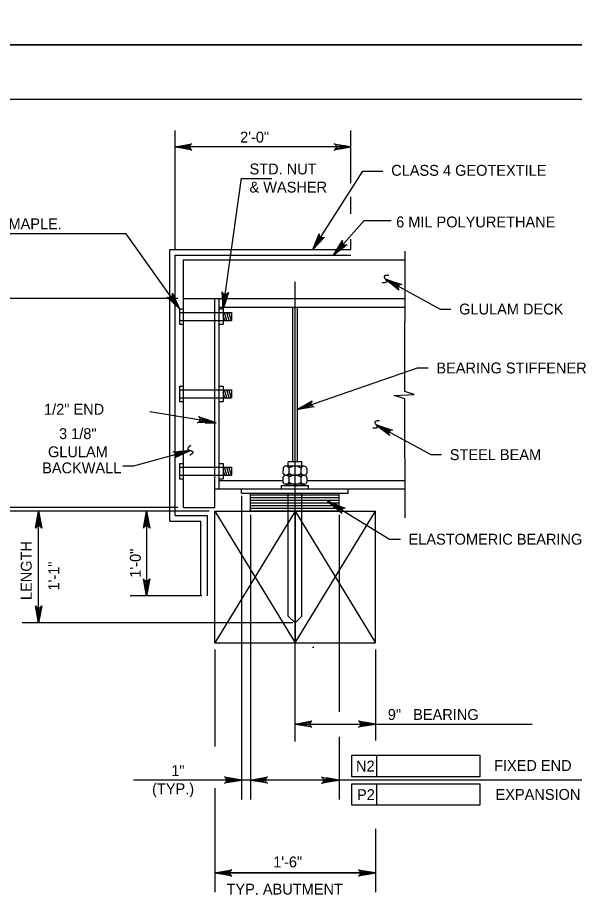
# Model space of a CAD drawing. Extents: x 638175 to 640495, y 294277 to 298435.
# Drawn here: x 639423 to 639576.6, y 297011.5 to 297255 of the extents above; entities that cross this region are included whole.
import ezdxf

# ---------------------------------------------------------------- set-up
doc = ezdxf.new("R2010")
doc.units = 0
for name, color, linetype in [('2', 7, 'Continuous'), ('3', 7, 'Continuous'), ('4', 7, 'Continuous'), ('5', 7, 'Continuous'), ('PLT-BNDY', 7, 'Continuous')]:
    doc.layers.add(name, color=color, linetype=linetype)

# ---------------------------------------------------------------- blocks, each defined once
blk = doc.blocks.new('25S')
at = {"layer": '4'}
blk.add_open_spline([(-1.68325, 0.611625), (-0.867125, -1.69875), (0.901125, 1.69875), (1.58125, -0.611625)], degree=2, dxfattribs=at)

msp = doc.modelspace()

# ---------------------------------------------------------------- linework, layer by layer
at = {"layer": '2'}
msp.add_line((639316.46, 297232.46), (640102.46, 297232.46), dxfattribs=at)
at = {"layer": '3'}
for p, q in [((639466.43, 297190.99), (639466.43, 297223.82)), ((639514.95, 297209.35), (639514.95, 297223.82)), ((639514.95, 297219.32), (639466.43, 297219.32)), ((639518.2, 297212.58), (639523.72, 297212.58)), ((639484.7, 297210.6), (639493.11, 297210.6)), ((639514.95, 297200.87), (639514.95, 297205.52)), ((639518.58, 297199.02), (639526.07, 297199.02)), ((639452.93, 297195.36), (639331.55, 297195.36)), ((639514.95, 297190.99), (639514.95, 297193.91)), ((639529.85, 297151.9), (639529.89, 297190.53)), ((639524.45, 297182.85), (639539.53, 297174.6)), ((639467.22, 297177.48), (639395.13, 297177.48)), ((639539.53, 297174.6), (639542.53, 297174.6)), ((639500.13, 297146.93), (639533.26, 297158.35)), ((639533.26, 297158.35), (639536.26, 297158.35)), ((639526.84, 297150.74), (639532.36, 297151.05)), ((639532.36, 297151.05), (639529.85, 297151.9)), ((639529.85, 297149.86), (639526.84, 297150.74)), ((639529.89, 297117.06), (639529.85, 297149.86)), ((639477.39, 297143.33), (639459.46, 297146.29)), ((639521.87, 297142.71), (639536.96, 297134.46)), ((639470.68, 297135.6), (639455, 297131.32)), ((639536.96, 297134.46), (639539.96, 297134.46)), ((639455, 297131.32), (639452, 297131.32)), ((639484.77, 297123.1), (639484.77, 297039.4)), ((639467.22, 297119.86), (639395.13, 297119.86)), ((639508.94, 297121.38), (639525.58, 297111.13)), ((639475.83, 297118.87), (639395.13, 297118.87)), ((639467.22, 297118.87), (639424.3, 297118.87)), ((639427.24, 297118.87), (639424.3, 297118.87)), ((639428.8, 297088.06), (639428.8, 297118.87)), ((639461.93, 297118.87), (639454.08, 297118.87)), ((639459.15, 297118.87), (639454.08, 297118.87)), ((639458.58, 297118.87), (639458.58, 297095.56)), ((639487.23, 297117.88), (639487.23, 297039.4)), ((639511.7, 297117.88), (639511.7, 297063.57)), ((639428.8, 297091.06), (639428.8, 297115.87)), ((639458.58, 297115.87), (639458.58, 297098.56)), ((639525.58, 297111.13), (639528.58, 297111.13)), ((639473.83, 297095.56), (639454.08, 297095.56)), ((639459.15, 297095.56), (639454.08, 297095.56)), ((639498.91, 297088.06), (639424.3, 297088.06)), ((639427.24, 297088.06), (639424.3, 297088.06)), ((639477.39, 297080.74), (639477.39, 297053.94)), ((639521.69, 297080.74), (639521.69, 297056.81)), ((639499.54, 297061.72), (639499.54, 297064.66)), ((639499.54, 297060.16), (639528.77, 297060.16)), ((639502.54, 297060.16), (639518.69, 297060.16)), ((639521.69, 297058.59), (639521.69, 297055.66)), ((639528.77, 297060.16), (639564.9, 297060.16)), ((639511.7, 297056.64), (639511.7, 297039.4)), ((639515.17, 297051.55), (639550.47, 297051.55)), ((639515.17, 297045.64), (639515.17, 297051.55)), ((639522.06, 297045.64), (639522.06, 297051.55)), ((639550.47, 297051.55), (639550.47, 297045.64)), ((639587.69, 297044.71), (639454.93, 297044.71)), ((639550.47, 297045.64), (639515.17, 297045.64)), ((639477.39, 297042.47), (639477.39, 297013.78)), ((639515.17, 297043.67), (639550.47, 297043.67)), ((639515.17, 297037.76), (639515.17, 297043.67)), ((639522.06, 297037.76), (639522.06, 297043.67)), ((639550.47, 297043.67), (639550.47, 297037.76)), ((639550.47, 297037.76), (639515.17, 297037.76)), ((639521.69, 297031.3), (639521.69, 297013.78)), ((639477.39, 297025.38), (639477.39, 297014.6)), ((639521.69, 297020.99), (639521.69, 297014.6)), ((639521.69, 297019.1), (639477.39, 297019.1)), ((639480.39, 297019.1), (639518.69, 297019.1))]:
    msp.add_line(p, q, dxfattribs=at)
for points in [[(639466.43, 297219.32), (639471.09, 297220.19), (639470.73, 297219.95), (639470.55, 297219.63), (639470.49, 297219.32), (639470.55, 297219.01), (639470.73, 297218.7), (639471.09, 297218.45), (639466.43, 297219.32), (639470.73, 297218.7), (639470.55, 297219.01), (639466.43, 297219.32), (639470.49, 297219.32), (639470.55, 297219.63), (639466.43, 297219.32), (639470.73, 297219.95)], [(639514.95, 297219.32), (639510.29, 297218.45), (639510.65, 297218.7), (639510.84, 297219.01), (639510.89, 297219.32), (639510.84, 297219.63), (639510.65, 297219.95), (639510.29, 297220.19), (639514.95, 297219.32), (639510.65, 297219.95), (639510.84, 297219.63), (639514.95, 297219.32), (639510.89, 297219.32), (639510.84, 297219.01), (639514.95, 297219.32), (639510.65, 297218.7)], [(639504.39, 297190.98), (639518.2, 297212.58)], [(639479.67, 297174.64), (639484.72, 297210.73)], [(639510.16, 297189.43), (639518.58, 297199.02)], [(639467.69, 297174.64), (639452.93, 297195.36)], [(639504.39, 297190.98), (639506.16, 297195.37), (639506.18, 297194.94), (639506.34, 297194.61), (639506.58, 297194.4), (639506.87, 297194.28), (639507.23, 297194.26), (639507.63, 297194.43), (639504.39, 297190.98), (639507.23, 297194.26), (639506.87, 297194.28), (639504.39, 297190.98), (639506.58, 297194.4), (639506.34, 297194.61), (639504.39, 297190.98), (639506.18, 297194.94)], [(639510.16, 297189.43), (639512.57, 297193.51), (639512.52, 297193.07), (639512.64, 297192.73), (639512.84, 297192.48), (639513.11, 297192.32), (639513.46, 297192.25), (639513.89, 297192.35), (639510.16, 297189.43), (639513.46, 297192.25), (639513.11, 297192.32), (639510.16, 297189.43), (639512.84, 297192.48), (639512.64, 297192.73), (639510.16, 297189.43), (639512.52, 297193.07)], [(639524.45, 297182.85), (639528.96, 297181.38), (639528.52, 297181.33), (639528.21, 297181.15), (639528.01, 297180.9), (639527.91, 297180.6), (639527.92, 297180.24), (639528.12, 297179.85), (639524.45, 297182.85), (639527.92, 297180.24), (639527.91, 297180.6), (639524.45, 297182.85), (639528.01, 297180.9), (639528.21, 297181.15), (639524.45, 297182.85), (639528.52, 297181.33)], [(639467.69, 297174.64), (639464.27, 297177.92), (639464.68, 297177.78), (639465.05, 297177.81), (639465.33, 297177.94), (639465.55, 297178.17), (639465.7, 297178.5), (639465.7, 297178.94), (639467.69, 297174.64), (639465.7, 297178.5), (639465.55, 297178.17), (639467.69, 297174.64), (639465.33, 297177.94), (639465.05, 297177.81), (639467.69, 297174.64), (639464.68, 297177.78)], [(639479.67, 297174.64), (639479.45, 297179.37), (639479.64, 297178.98), (639479.93, 297178.75), (639480.23, 297178.66), (639480.55, 297178.67), (639480.88, 297178.81), (639481.18, 297179.13), (639479.67, 297174.64), (639480.88, 297178.81), (639480.55, 297178.67), (639479.67, 297174.64), (639480.23, 297178.66), (639479.93, 297178.75), (639479.67, 297174.64), (639479.64, 297178.98)], [(639500.13, 297146.93), (639504.25, 297149.28), (639503.99, 297148.92), (639503.92, 297148.57), (639503.97, 297148.26), (639504.13, 297147.98), (639504.4, 297147.74), (639504.82, 297147.62), (639500.13, 297146.93), (639504.4, 297147.74), (639504.13, 297147.98), (639500.13, 297146.93), (639503.97, 297148.26), (639503.92, 297148.57), (639500.13, 297146.93), (639503.99, 297148.92)], [(639477.39, 297143.33), (639472.65, 297143.23), (639473.05, 297143.42), (639473.28, 297143.7), (639473.39, 297144), (639473.38, 297144.31), (639473.25, 297144.65), (639472.94, 297144.95), (639477.39, 297143.33), (639473.25, 297144.65), (639473.38, 297144.31), (639477.39, 297143.33), (639473.39, 297144), (639473.28, 297143.7), (639477.39, 297143.33), (639473.05, 297143.42)], [(639521.87, 297142.71), (639526.38, 297141.24), (639525.95, 297141.19), (639525.63, 297141.01), (639525.44, 297140.76), (639525.33, 297140.46), (639525.35, 297140.1), (639525.54, 297139.71), (639521.87, 297142.71), (639525.35, 297140.1), (639525.33, 297140.46), (639521.87, 297142.71), (639525.44, 297140.76), (639525.63, 297141.01), (639521.87, 297142.71), (639525.95, 297141.19)], [(639470.68, 297135.6), (639466.41, 297133.53), (639466.69, 297133.87), (639466.79, 297134.22), (639466.76, 297134.53), (639466.63, 297134.82), (639466.37, 297135.07), (639465.95, 297135.22), (639470.68, 297135.6), (639466.37, 297135.07), (639466.63, 297134.82), (639470.68, 297135.6), (639466.76, 297134.53), (639466.79, 297134.22), (639470.68, 297135.6), (639466.69, 297133.87)], [(639508.94, 297121.38), (639513.37, 297119.68), (639512.93, 297119.66), (639512.61, 297119.49), (639512.4, 297119.25), (639512.28, 297118.96), (639512.28, 297118.59), (639512.45, 297118.19), (639508.94, 297121.38), (639512.28, 297118.59), (639512.28, 297118.96), (639508.94, 297121.38), (639512.4, 297119.25), (639512.61, 297119.49), (639508.94, 297121.38), (639512.93, 297119.66)], [(639428.8, 297118.87), (639429.68, 297114.21), (639429.43, 297114.57), (639429.12, 297114.76), (639428.8, 297114.81), (639428.49, 297114.76), (639428.18, 297114.57), (639427.93, 297114.21), (639428.8, 297118.87), (639428.18, 297114.57), (639428.49, 297114.76), (639428.8, 297118.87), (639428.8, 297114.81), (639429.12, 297114.76), (639428.8, 297118.87), (639429.43, 297114.57)], [(639458.58, 297118.87), (639459.45, 297114.21), (639459.2, 297114.57), (639458.89, 297114.76), (639458.58, 297114.81), (639458.26, 297114.76), (639457.95, 297114.57), (639457.7, 297114.21), (639458.58, 297118.87), (639457.95, 297114.57), (639458.26, 297114.76), (639458.58, 297118.87), (639458.58, 297114.81), (639458.89, 297114.76), (639458.58, 297118.87), (639459.2, 297114.57)], [(639458.58, 297095.56), (639457.7, 297100.22), (639457.95, 297099.86), (639458.26, 297099.67), (639458.58, 297099.62), (639458.89, 297099.67), (639459.2, 297099.86), (639459.45, 297100.22), (639458.58, 297095.56), (639459.2, 297099.86), (639458.89, 297099.67), (639458.58, 297095.56), (639458.58, 297099.62), (639458.26, 297099.67), (639458.58, 297095.56), (639457.95, 297099.86)], [(639428.8, 297088.06), (639427.93, 297092.72), (639428.18, 297092.36), (639428.49, 297092.18), (639428.8, 297092.12), (639429.12, 297092.18), (639429.43, 297092.36), (639429.68, 297092.72), (639428.8, 297088.06), (639429.43, 297092.36), (639429.12, 297092.18), (639428.8, 297088.06), (639428.8, 297092.12), (639428.49, 297092.18), (639428.8, 297088.06), (639428.18, 297092.36)], [(639499.54, 297060.16), (639504.2, 297061.03), (639503.84, 297060.78), (639503.66, 297060.47), (639503.6, 297060.16), (639503.66, 297059.84), (639503.84, 297059.53), (639504.2, 297059.28), (639499.54, 297060.16), (639503.84, 297059.53), (639503.66, 297059.84), (639499.54, 297060.16), (639503.6, 297060.16), (639503.66, 297060.47), (639499.54, 297060.16), (639503.84, 297060.78)], [(639521.69, 297060.16), (639517.03, 297059.28), (639517.39, 297059.53), (639517.57, 297059.84), (639517.63, 297060.16), (639517.57, 297060.47), (639517.39, 297060.78), (639517.03, 297061.03), (639521.69, 297060.16), (639517.39, 297060.78), (639517.57, 297060.47), (639521.69, 297060.16), (639517.63, 297060.16), (639517.57, 297059.84), (639521.69, 297060.16), (639517.39, 297059.53)], [(639484.71, 297044.7), (639480.04, 297043.83), (639480.4, 297044.08), (639480.59, 297044.39), (639480.64, 297044.7), (639480.59, 297045.02), (639480.4, 297045.33), (639480.04, 297045.58), (639484.71, 297044.7), (639480.4, 297045.33), (639480.59, 297045.02), (639484.71, 297044.7), (639480.64, 297044.7), (639480.59, 297044.39), (639484.71, 297044.7), (639480.4, 297044.08)], [(639487.23, 297044.71), (639491.89, 297045.59), (639491.53, 297045.34), (639491.35, 297045.03), (639491.29, 297044.71), (639491.35, 297044.4), (639491.53, 297044.09), (639491.89, 297043.84), (639487.23, 297044.71), (639491.53, 297044.09), (639491.35, 297044.4), (639487.23, 297044.71), (639491.29, 297044.71), (639491.35, 297045.03), (639487.23, 297044.71), (639491.53, 297045.34)], [(639511.49, 297044.68), (639506.83, 297043.81), (639507.18, 297044.05), (639507.37, 297044.37), (639507.42, 297044.68), (639507.37, 297044.99), (639507.18, 297045.3), (639506.83, 297045.55), (639511.49, 297044.68), (639507.18, 297045.3), (639507.37, 297044.99), (639511.49, 297044.68), (639507.42, 297044.68), (639507.37, 297044.37), (639511.49, 297044.68), (639507.18, 297044.05)]]:
    msp.add_lwpolyline(points, dxfattribs=at)
for points in [[(639469.43, 297219.82), (639469.43, 297218.82), (639466.43, 297219.32)], [(639511.95, 297219.82), (639511.95, 297218.82), (639514.95, 297219.32)], [(639504.39, 297190.98), (639506.21, 297193.37), (639505.79, 297193.64)], [(639510.16, 297189.43), (639512.32, 297191.52), (639511.95, 297191.85)], [(639526.84, 297180.97), (639527.32, 297181.85), (639524.45, 297182.85)], [(639467.69, 297174.64), (639466.15, 297177.22), (639465.74, 297176.93)], [(639479.67, 297174.64), (639480.33, 297177.57), (639479.84, 297177.64)], [(639503.25, 297147.48), (639502.92, 297148.42), (639500.25, 297146.97)], [(639474.89, 297144.25), (639474.73, 297143.27), (639477.77, 297143.27)], [(639524.27, 297140.83), (639524.75, 297141.7), (639521.88, 297142.71)], [(639467.63, 297135.29), (639467.89, 297134.32), (639470.65, 297135.59)], [(639510.79, 297119.65), (639511.32, 297120.5), (639508.5, 297121.65)], [(639428.3, 297115.87), (639429.3, 297115.87), (639428.8, 297118.87)], [(639458.08, 297115.87), (639459.08, 297115.87), (639458.58, 297118.87)], [(639458.08, 297098.56), (639459.08, 297098.56), (639458.58, 297095.56)], [(639428.3, 297091.06), (639429.3, 297091.06), (639428.8, 297088.06)], [(639502.54, 297060.66), (639502.54, 297059.66), (639499.54, 297060.16)], [(639518.69, 297060.66), (639518.69, 297059.66), (639521.69, 297060.16)], [(639481.23, 297045.3), (639481.23, 297044.12), (639484.77, 297044.71)], [(639490.78, 297045.3), (639490.78, 297044.12), (639487.23, 297044.71)], [(639508.15, 297045.3), (639508.15, 297044.12), (639511.7, 297044.71)], [(639480.39, 297019.6), (639480.39, 297018.6), (639477.39, 297019.1)], [(639518.69, 297019.6), (639518.69, 297018.6), (639521.69, 297019.1)]]:
    msp.add_lwpolyline(points, close=True, dxfattribs=at)
at = {"layer": '4'}
for p, q in [((639467.69, 297174.64), (639468.78, 297174.64)), ((639467.69, 297174.64), (639467.69, 297170.47)), ((639467.69, 297173.65), (639478.58, 297173.65)), ((639478.58, 297174.64), (639479.67, 297174.64)), ((639478.58, 297173.65), (639481.99, 297173.65)), ((639479.67, 297174.64), (639479.67, 297170.47)), ((639480.13, 297171.46), (639479.67, 297172.9)), ((639480.75, 297171.46), (639480.05, 297173.65)), ((639481.37, 297171.46), (639480.67, 297173.65)), ((639481.99, 297171.46), (639481.29, 297173.65)), ((639481.99, 297173.65), (639481.99, 297171.46)), ((639500.13, 297175.13), (639500.13, 297132.43)), ((639467.69, 297171.46), (639478.58, 297171.46)), ((639467.69, 297170.47), (639468.78, 297170.47)), ((639478.58, 297171.46), (639481.99, 297171.46)), ((639478.58, 297170.47), (639479.67, 297170.47)), ((639467.69, 297153.31), (639467.69, 297149.15)), ((639467.69, 297153.31), (639468.78, 297153.31)), ((639467.69, 297152.32), (639478.58, 297152.32)), ((639478.58, 297153.31), (639479.67, 297153.31)), ((639478.58, 297152.32), (639481.99, 297152.32)), ((639479.67, 297153.31), (639479.67, 297149.15)), ((639480.13, 297150.13), (639479.67, 297151.57)), ((639480.75, 297150.13), (639480.05, 297152.32)), ((639481.37, 297150.13), (639480.67, 297152.32)), ((639481.99, 297150.13), (639481.29, 297152.32)), ((639481.99, 297152.32), (639481.99, 297150.13)), ((639467.69, 297150.13), (639478.58, 297150.13)), ((639467.69, 297149.15), (639468.78, 297149.15)), ((639478.58, 297150.13), (639481.99, 297150.13)), ((639478.58, 297149.15), (639479.67, 297149.15)), ((639467.69, 297131.98), (639468.78, 297131.98)), ((639467.69, 297131.98), (639467.69, 297127.82)), ((639478.58, 297131.98), (639479.67, 297131.98)), ((639479.67, 297131.98), (639479.67, 297127.82)), ((639467.69, 297130.99), (639478.58, 297130.99)), ((639478.58, 297130.99), (639481.99, 297130.99)), ((639480.13, 297128.8), (639479.67, 297130.25)), ((639480.75, 297128.8), (639480.05, 297130.99)), ((639481.37, 297128.8), (639480.67, 297130.99)), ((639481.99, 297128.8), (639481.29, 297130.99)), ((639481.99, 297130.99), (639481.99, 297128.8)), ((639467.69, 297128.8), (639478.58, 297128.8)), ((639467.69, 297127.82), (639468.78, 297127.82)), ((639478.58, 297128.8), (639481.99, 297128.8)), ((639478.58, 297127.82), (639479.67, 297127.82)), ((639514.05, 297083), (639514.05, 297083)), ((639521.65, 297083.41), (639521.65, 297083.41)), ((639501.64, 297081.37), (639501.64, 297081.37)), ((639504.34, 297081.16), (639504.58, 297081.45)), ((639504.63, 297081.19), (639504.59, 297081.45)), ((639505.37, 297081.86), (639505.37, 297081.86)), ((639516.68, 297082.77), (639516.68, 297082.77)), ((639486.77, 297079.41), (639486.77, 297079.41))]:
    msp.add_line(p, q, dxfattribs=at)
for points in [[(639477.39, 297019.1), (639482.06, 297019.97), (639481.7, 297019.72), (639481.51, 297019.41), (639481.46, 297019.1), (639481.51, 297018.78), (639481.7, 297018.47), (639482.06, 297018.22), (639477.39, 297019.1), (639481.7, 297018.47), (639481.51, 297018.78), (639477.39, 297019.1), (639481.46, 297019.1), (639481.51, 297019.41), (639477.39, 297019.1), (639481.7, 297019.72)], [(639521.69, 297019.1), (639517.03, 297018.22), (639517.39, 297018.47), (639517.57, 297018.78), (639517.63, 297019.1), (639517.57, 297019.41), (639517.39, 297019.72), (639517.03, 297019.97), (639521.69, 297019.1), (639517.39, 297019.72), (639517.57, 297019.41), (639521.69, 297019.1), (639517.63, 297019.1), (639517.57, 297018.78), (639521.69, 297019.1), (639517.39, 297018.47)]]:
    msp.add_lwpolyline(points, dxfattribs=at)
at = {"layer": '5'}
for p, q in [((639465.04, 297190.98), (639514.95, 297190.98)), ((639465.04, 297116.12), (639465.04, 297190.98)), ((639466.43, 297189.43), (639514.95, 297189.43)), ((639466.43, 297117.67), (639466.43, 297189.43)), ((639468.78, 297119.86), (639468.78, 297188.15)), ((639468.78, 297188.15), (639529.88, 297188.15)), ((639499.54, 297055.36), (639499.54, 297182.14)), ((639468.78, 297177.48), (639529.88, 297177.48)), ((639477.39, 297119.86), (639477.39, 297177.48)), ((639478.58, 297124.98), (639478.58, 297177.48)), ((639478.58, 297175.13), (639529.88, 297175.13)), ((639498.95, 297132.43), (639498.95, 297175.13)), ((639497.67, 297131.28), (639497.67, 297132.44)), ((639501.42, 297132.43), (639497.67, 297132.44)), ((639501.42, 297131.27), (639501.42, 297132.43)), ((639496.21, 297130.7), (639496.2, 297129.36)), ((639502.01, 297131.27), (639497.03, 297131.28)), ((639497.9, 297129.36), (639497.91, 297130.7)), ((639501.18, 297129.35), (639501.19, 297130.69)), ((639502.77, 297130.69), (639502.77, 297129.35)), ((639478.58, 297127.32), (639496.2, 297127.32)), ((639496.2, 297128.2), (639496.2, 297126.86)), ((639502, 297128.77), (639497.02, 297128.78)), ((639497.9, 297126.86), (639497.9, 297128.2)), ((639501.18, 297126.85), (639501.18, 297128.19)), ((639502.76, 297128.19), (639502.76, 297126.85)), ((639502.76, 297127.32), (639529.88, 297127.32)), ((639477.39, 297124.98), (639529.88, 297124.98)), ((639484.77, 297123.8), (639484.77, 297124.98)), ((639495.8, 297125.96), (639503.28, 297125.96)), ((639495.8, 297124.98), (639495.8, 297125.96)), ((639502, 297126.27), (639497.02, 297126.28)), ((639497.67, 297125.96), (639497.67, 297126.28)), ((639501.42, 297125.96), (639501.42, 297126.27)), ((639503.28, 297124.98), (639503.28, 297125.96)), ((639514.16, 297123.8), (639514.16, 297124.98)), ((639484.77, 297123.8), (639514.16, 297123.8)), ((639487.23, 297118.87), (639487.23, 297123.8)), ((639487.23, 297123.4), (639497.67, 297123.4)), ((639487.23, 297122.66), (639497.67, 297122.66)), ((639487.23, 297121.92), (639497.67, 297121.92)), ((639497.67, 297118.87), (639497.67, 297123.8)), ((639497.67, 297123.4), (639499.54, 297123.4)), ((639497.67, 297122.66), (639499.54, 297122.66)), ((639497.67, 297121.92), (639499.54, 297121.92)), ((639499.54, 297123.4), (639501.42, 297123.4)), ((639499.54, 297122.66), (639501.42, 297122.66)), ((639499.54, 297121.92), (639501.42, 297121.92)), ((639501.42, 297118.87), (639501.42, 297123.8)), ((639501.42, 297123.4), (639511.7, 297123.4)), ((639501.42, 297122.66), (639511.7, 297122.66)), ((639501.42, 297121.92), (639511.7, 297121.92)), ((639511.7, 297118.87), (639511.7, 297123.8)), ((639468.78, 297119.86), (639477.39, 297119.86)), ((639487.23, 297121.18), (639497.67, 297121.18)), ((639487.23, 297120.45), (639497.67, 297120.45)), ((639487.23, 297119.71), (639497.67, 297119.71)), ((639497.67, 297121.18), (639499.54, 297121.18)), ((639497.67, 297120.45), (639499.54, 297120.45)), ((639497.67, 297119.71), (639499.54, 297119.71)), ((639499.54, 297121.18), (639501.42, 297121.18)), ((639499.54, 297120.45), (639501.42, 297120.45)), ((639499.54, 297119.71), (639501.42, 297119.71)), ((639501.42, 297121.18), (639511.7, 297121.18)), ((639501.42, 297120.45), (639511.7, 297120.45)), ((639501.42, 297119.71), (639511.7, 297119.71)), ((639466.43, 297117.67), (639475.39, 297117.67)), ((639475.39, 297095.56), (639475.39, 297117.67)), ((639477.39, 297082.58), (639477.39, 297118.87)), ((639477.39, 297118.87), (639521.69, 297118.87)), ((639499.54, 297118.87), (639477.39, 297082.58)), ((639477.39, 297118.87), (639499.54, 297082.58)), ((639487.23, 297118.97), (639497.67, 297118.97)), ((639497.67, 297118.97), (639499.54, 297118.97)), ((639497.67, 297089.92), (639497.67, 297118.87)), ((639499.54, 297118.97), (639501.42, 297118.97)), ((639499.54, 297082.58), (639521.69, 297118.87)), ((639499.54, 297118.87), (639521.69, 297082.58)), ((639499.54, 297118.87), (639499.54, 297082.58)), ((639501.42, 297118.97), (639511.7, 297118.97)), ((639501.42, 297089.9), (639501.42, 297118.87)), ((639521.69, 297082.84), (639521.69, 297118.87)), ((639465.04, 297116.12), (639473.53, 297116.12)), ((639473.53, 297095.56), (639473.53, 297116.12)), ((639499.55, 297088.04), (639497.66, 297089.92)), ((639499.55, 297088.04), (639501.41, 297089.9)), ((639477.39, 297082.58), (639521.69, 297082.58))]:
    msp.add_line(p, q, dxfattribs=at)
for centre, radius, start, end in [((639497.05, 297129.69), 0.912, 201.1685, 271.7086), ((639497.05, 297130.37), 0.912, 88.0545, 158.5946), ((639497.05, 297130.37), 0.912, 21.1685, 88.0545), ((639497.05, 297129.69), 0.912, 271.7086, 338.5946), ((639499.54, 297128.67), 2.61, 50.9315, 128.8315), ((639499.55, 297131.39), 2.61, 230.9315, 308.8315), ((639501.97, 297129.6), 0.829, 197.3333, 342.4297), ((639501.98, 297130.44), 0.829, 17.3333, 162.4297), ((639497.05, 297127.87), 0.912, 88.0545, 158.5946), ((639497.05, 297127.19), 0.912, 201.1685, 271.7086), ((639497.05, 297127.19), 0.912, 271.7086, 338.5946), ((639497.05, 297127.87), 0.912, 21.1685, 88.0545), ((639499.54, 297126.17), 2.61, 50.9315, 128.8315), ((639499.54, 297128.89), 2.61, 230.9315, 308.8315), ((639501.97, 297127.94), 0.829, 17.3333, 162.4297), ((639501.97, 297127.1), 0.829, 197.3333, 342.4297)]:
    msp.add_arc(centre, radius, start, end, dxfattribs=at)
at = {"layer": 'PLT-BNDY'}
for points in [[(639276.46, 297841.46), (640117.46, 297841.46), (640117.46, 297247.46), (639276.46, 297247.46)], [(639276.46, 297247.46), (640117.46, 297247.46), (640117.46, 296653.46), (639276.46, 296653.46)]]:
    msp.add_lwpolyline(points, close=True, dxfattribs=at)

# ---------------------------------------------------------------- block references
at = {"layer": '4', "yscale": 0.7874015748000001}
for p, xscale, rotation in [((639524.45, 297182.85), 0.7874015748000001, -112.31681079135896), ((639521.88, 297142.71), 0.7874015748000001, -112.31681079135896), ((639470.65, 297135.59), 0.7874015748, -74.14105771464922)]:
    msp.add_blockref('25S', p, dxfattribs=dict(at, xscale=xscale, rotation=rotation))

# ---------------------------------------------------------------- texts
at = {"layer": '3'}
for s, p in [('2\'-0"', (639484.38, 297220.52)), ('STD. NUT', (639486.97, 297211.73)), ('CLASS 4 GEOTEXTILE', (639526.05, 297211.35)), ('& WASHER', (639486.97, 297206.73)), ('WASHER FOR NORTHERN RED OAK AND RED MAPLE.', (639330, 297196.62)), ('6 MIL POLYURETHANE', (639527.41, 297197.12)), ('GLULAM DECK', (639544.78, 297173.1)), ('BEARING STIFFENER', (639538.51, 297156.85)), ('1/2" END  ', (639430.3, 297145.47)), ('3 1/8"', (639434.44, 297138.74)), ('GLULAM', (639431.39, 297133.74)), ('STEEL BEAM', (639542.21, 297132.95)), ('BACKWALL', (639429.78, 297129.3)), ('ELASTOMERIC BEARING PAD', (639530.83, 297109.63)), ('9"   BEARING', (639525.11, 297061.29)), ('1"', (639465.38, 297045.82)), ('N2', (639516.34, 297047.07)), ('FIXED END', (639554.41, 297047.24)), ('(TYP.)', (639460.1, 297040.82)), ('P2', (639516.62, 297039.19)), ('EXPANSION END', (639554.82, 297039.25)), ('1\'-6"', (639493.5, 297020.64)), ('TYP. ABUTMENT', (639480.63, 297013.14))]:
    msp.add_text(s, height=3, dxfattribs=at).set_placement(p)
for s, p in [('LENGTH', (639426.9, 297094.36)), ('1\'-0"', (639456.98, 297100.52)), ('1\'-1"', (639434.49, 297096.98))]:
    msp.add_text(s, height=3, rotation=90, dxfattribs=at).set_placement(p)

doc.saveas('drawing.dxf')
